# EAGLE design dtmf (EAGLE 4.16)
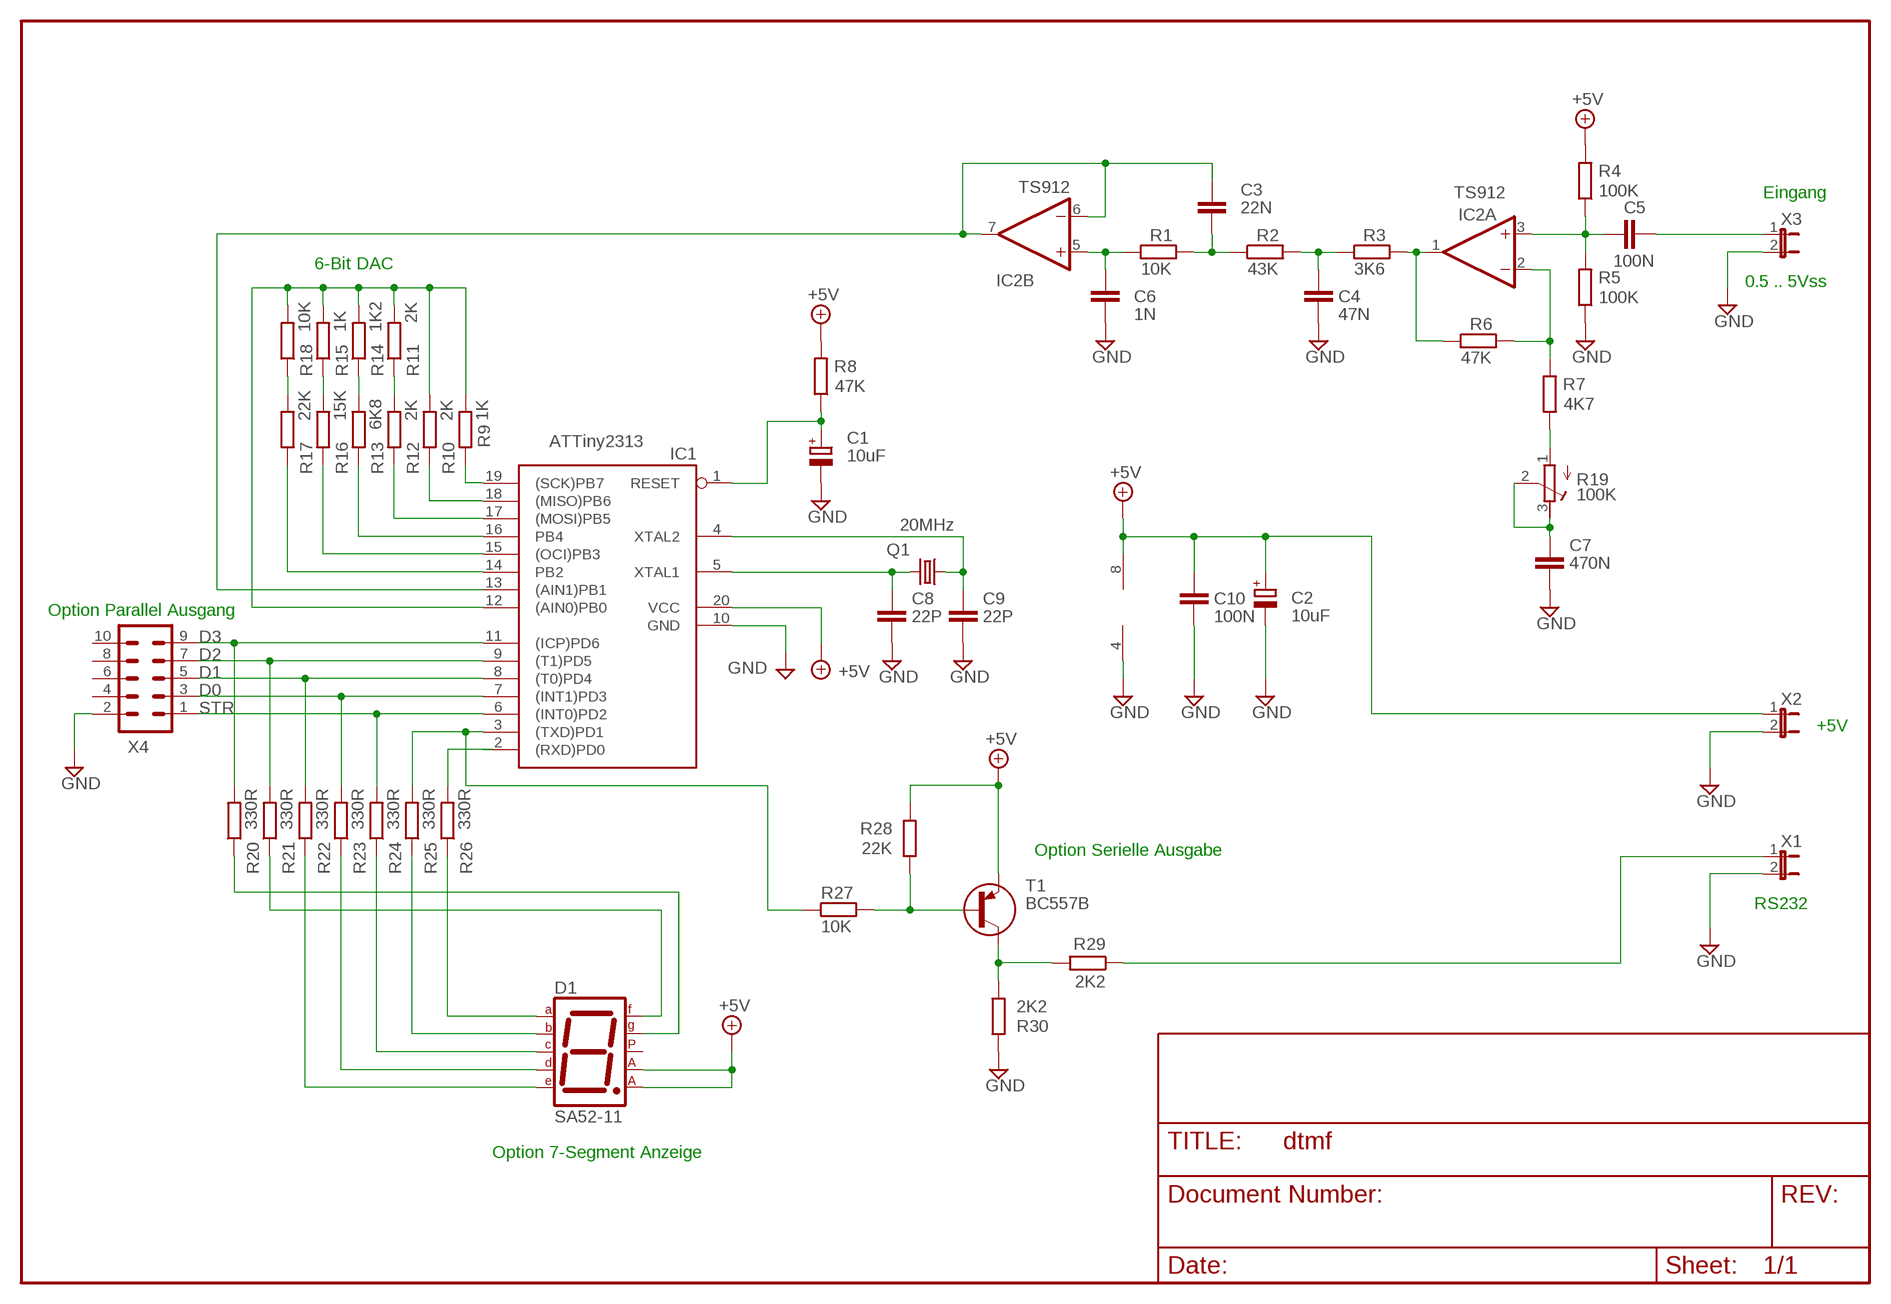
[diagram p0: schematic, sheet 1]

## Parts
C1  10uF  CPOL-EUE2.5-6  [E2,5-6]
C2  10uF  CPOL-EUE2.5-6  [E2,5-6]
C3  22N  C-EU050-025X075  [C050-025X075]
C4  47N  C-EU050-025X075  [C050-025X075]
C5  100N  C-EU050-025X075  [C050-025X075]
C6  1N  C-EU050-025X075  [C050-025X075]
C7  470N  C-EU050-025X075  [C050-025X075]
C8  22P  C-EU025-024X044  [C025-024X044]
C9  22P  C-EU025-024X044  [C025-024X044]
C10  100N  C-EU050-024X044  [C050-024X044]
D1  SA52-11  7SEG-CA  [7SEG-13]
IC1  ATTiny2313  AT90S2313P  [DIL20]
IC2  TS912  TLC272P  [DIL08]
Q1  20MHz  CRYSTALHC18U-V  [HC18U-V]
R1  10K  R-EU_0207/10  [0207/10]
R2  43K  R-EU_0207/10  [0207/10]
R3  3K6  R-EU_0207/10  [0207/10]
R4  100K  R-EU_0207/10  [0207/10]
R5  100K  R-EU_0207/10  [0207/10]
R6  47K  R-EU_0207/10  [0207/10]
R7  4K7  R-EU_0207/10  [0207/10]
R8  47K  R-EU_0207/10  [0207/10]
R9  1K  R-EU_0207/10  [0207/10]
R10  2K  R-EU_0207/10  [0207/10]
R11  2K  R-EU_0207/10  [0207/10]
R12  2K  R-EU_0207/10  [0207/10]
R13  6K8  R-EU_0207/10  [0207/10]
R14  1K2  R-EU_0207/10  [0207/10]
R15  1K  R-EU_0207/10  [0207/10]
R16  15K  R-EU_0207/10  [0207/10]
R17  22K  R-EU_0207/10  [0207/10]
R18  10K  R-EU_0207/10  [0207/10]
R19  100K  R-TRIMM64Y  [RTRIM64Y]
R20  330R  R-EU_0207/10  [0207/10]
R21  330R  R-EU_0207/10  [0207/10]
R22  330R  R-EU_0207/10  [0207/10]
R23  330R  R-EU_0207/10  [0207/10]
R24  330R  R-EU_0207/10  [0207/10]
R25  330R  R-EU_0207/10  [0207/10]
R26  330R  R-EU_0207/10  [0207/10]
R27  10K  R-EU_0207/10  [0207/10]
R28  22K  R-EU_0207/10  [0207/10]
R29  2K2  R-EU_0207/10  [0207/10]
R30  2K2  R-EU_0207/10  [0207/10]
T1  BC557B  BC559B-PNP-TO92-EBC  [TO92-EBC]
X1  JP1E  [JP1]
X2  JP1E  [JP1]
X3  JP1E  [JP1]
X4  MA05-2  [MA05-2]

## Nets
+5V: C2.+ C10.1 D1.3(CA1) D1.8(CA2) IC1.20(VCC) IC2.8(P:V+) R4.2 R8.2 R28.2 T1.E X2.1
D0: IC1.7((INT1)PD3) R23.2 X4.3
D1: IC1.8((T0)PD4) R22.2 X4.5
D2: IC1.9((T1)PD5) R21.2 X4.7
D3: IC1.11((ICP)PD6) R20.2 X4.9
GND: C1.- C2.- C4.2 C6.2 C7.2 C8.2 C9.2 C10.2 IC1.10(GND) IC2.4(P:V-) R5.1 R30.2 X1.2 X2.2 X3.2 X4.2
N$1: IC1.19((SCK)PB7) R9.1
N$2: IC1.18((MISO)PB6) R10.1
N$3: IC1.17((MOSI)PB5) R12.1
N$4: IC1.16(PB4) R13.1
N$5: IC1.15((OCI)PB3) R16.1
N$6: IC1.14(PB2) R17.1
N$7: R17.2 R18.1
N$8: R15.1 R16.2
N$9: R13.2 R14.1
N$10: R11.1 R12.2
N$11: IC1.12((AIN0)PB0) R9.2 R10.2 R11.2 R14.2 R15.2 R18.2
N$12: C7.1 R19.2(S) R19.3(A)
N$13: C1.+ IC1.1(RESET) R8.1
N$14: C9.1 IC1.4(XTAL2) Q1.1
N$15: C8.1 IC1.5(XTAL1) Q1.2
N$16: C3.1 IC1.13((AIN1)PB1) IC2.6(B:-IN) IC2.7(B:OUT)
N$18: C6.1 IC2.5(B:+IN) R1.1
N$19: C3.2 R1.2 R2.1
N$20: C4.1 R2.2 R3.1
N$21: IC2.1(A:OUT) R3.2 R6.1
N$22: C5.1 IC2.3(A:+IN) R4.1 R5.2
N$23: IC2.2(A:-IN) R6.2 R7.2
N$24: R7.1 R19.1(E)
N$29: IC1.3((TXD)PD1) R25.2 R27.1
N$30: IC1.2((RXD)PD0) R26.2
N$31: D1.7(A) R26.1
N$32: D1.6(B) R25.1
N$33: D1.4(C) R24.1
N$34: D1.2(D) R23.1
N$35: D1.1(E) R22.1
N$36: D1.9(F) R21.1
N$37: D1.10(G) R20.1
N$38: R27.2 R28.1 T1.B
N$40: R29.2 R30.1 T1.C
N$41: R29.1 X1.1
N$42: C5.2 X3.1
STR: IC1.6((INT0)PD2) R24.2 X4.1
Unconnected: D1.5(DP) X4.4 X4.6 X4.8 X4.10

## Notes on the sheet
- Eingang
- 6-Bit DAC
- 0.5 .. 5Vss
- Option Parallel Ausgang
- +5V
- Option Serielle Ausgabe
- RS232
- Option 7-Segment Anzeige

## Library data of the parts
C1 C2 = rcl:CPOL-EU: POLARIZED CAPACITOR, European symbol
C3-C10 = rcl:C-EU: CAPACITOR, European symbol
D1 = special:7SEG-CA: 7-segment DISPLAY single anode, 13 mm
IC1 = atmel:AT90S2313: MICROCONTROLLER 2 Kbytes FLASH 128 bytes SRAM 128 bytes EEPROM UART
IC2 = linear:TLC272: OP AMP
Q1 = crystal:CRYSTAL: CRYSTAL
R1-R18 R20-R30 = rcl:R-EU_: RESISTOR, European symbol
R19 = rcl:R-TRIMM: Trimm resistor
T1 = transistor:*-PNP-: PNP Transistror
X1-X3 = jumper:JP1E: JUMPER
X4 = con-lstb:MA05-2: PIN HEADER

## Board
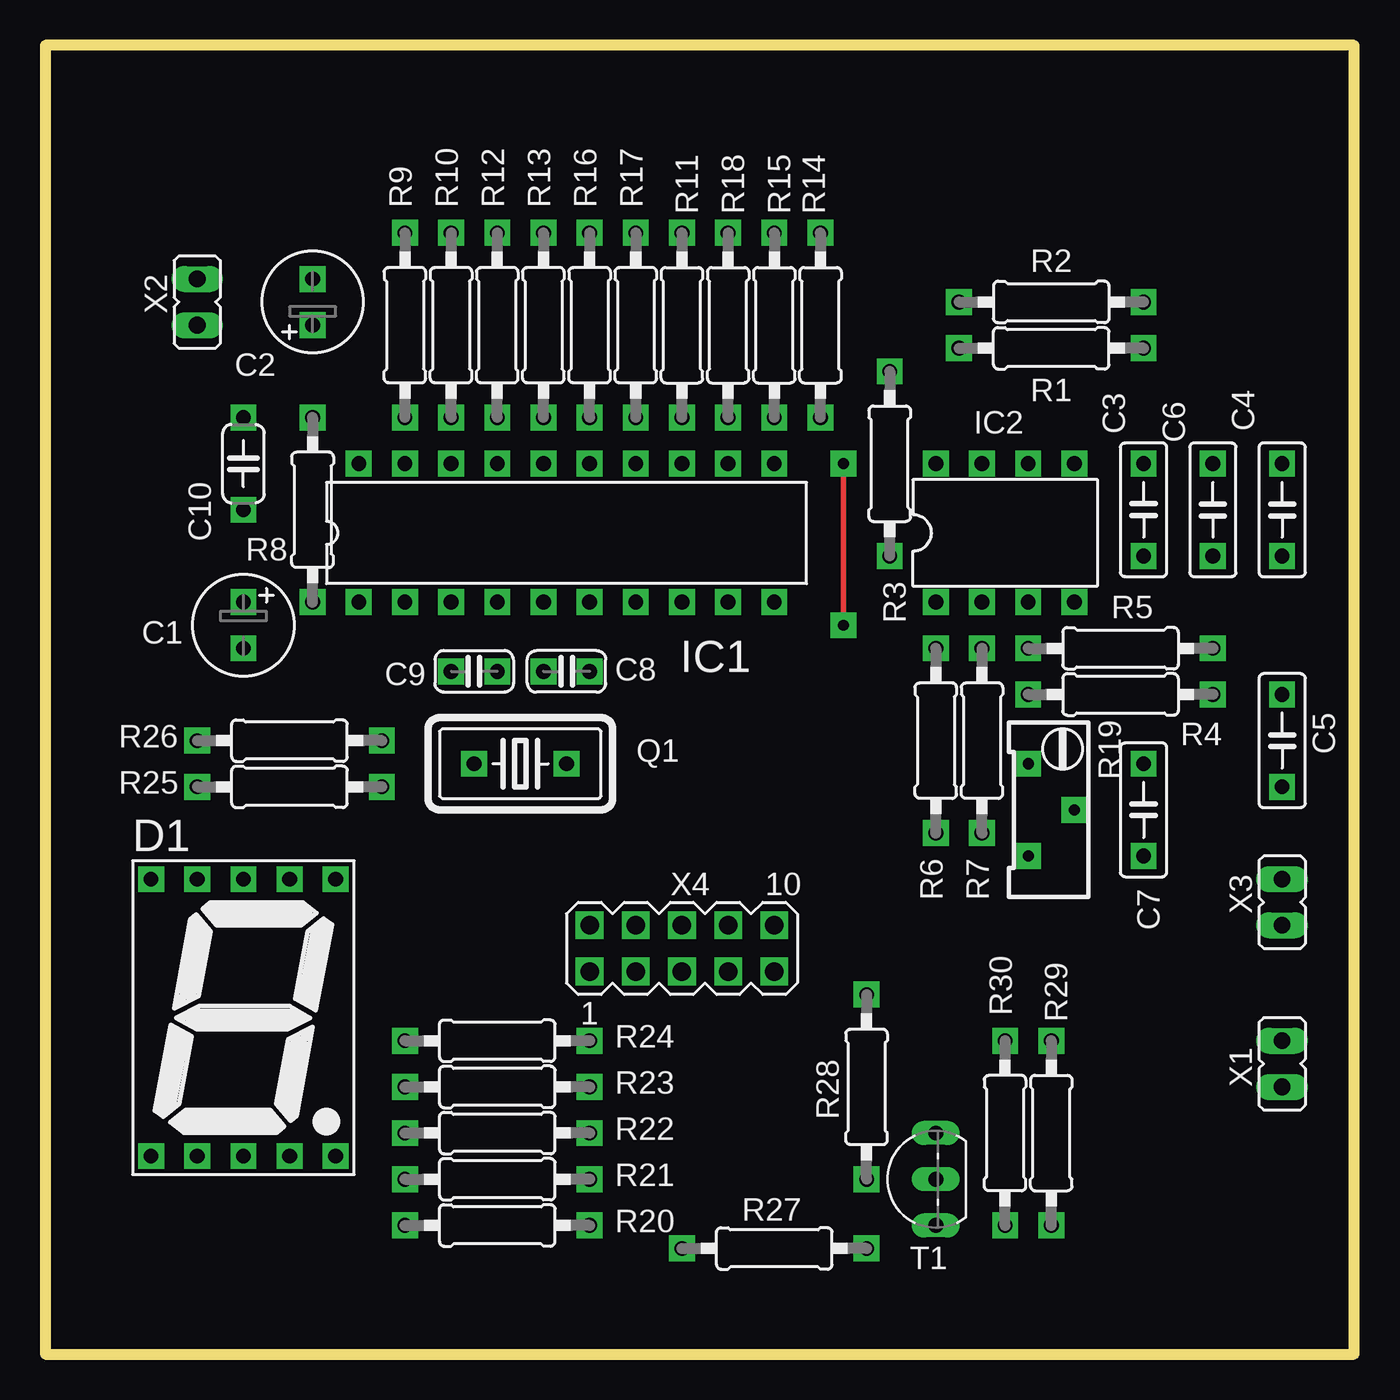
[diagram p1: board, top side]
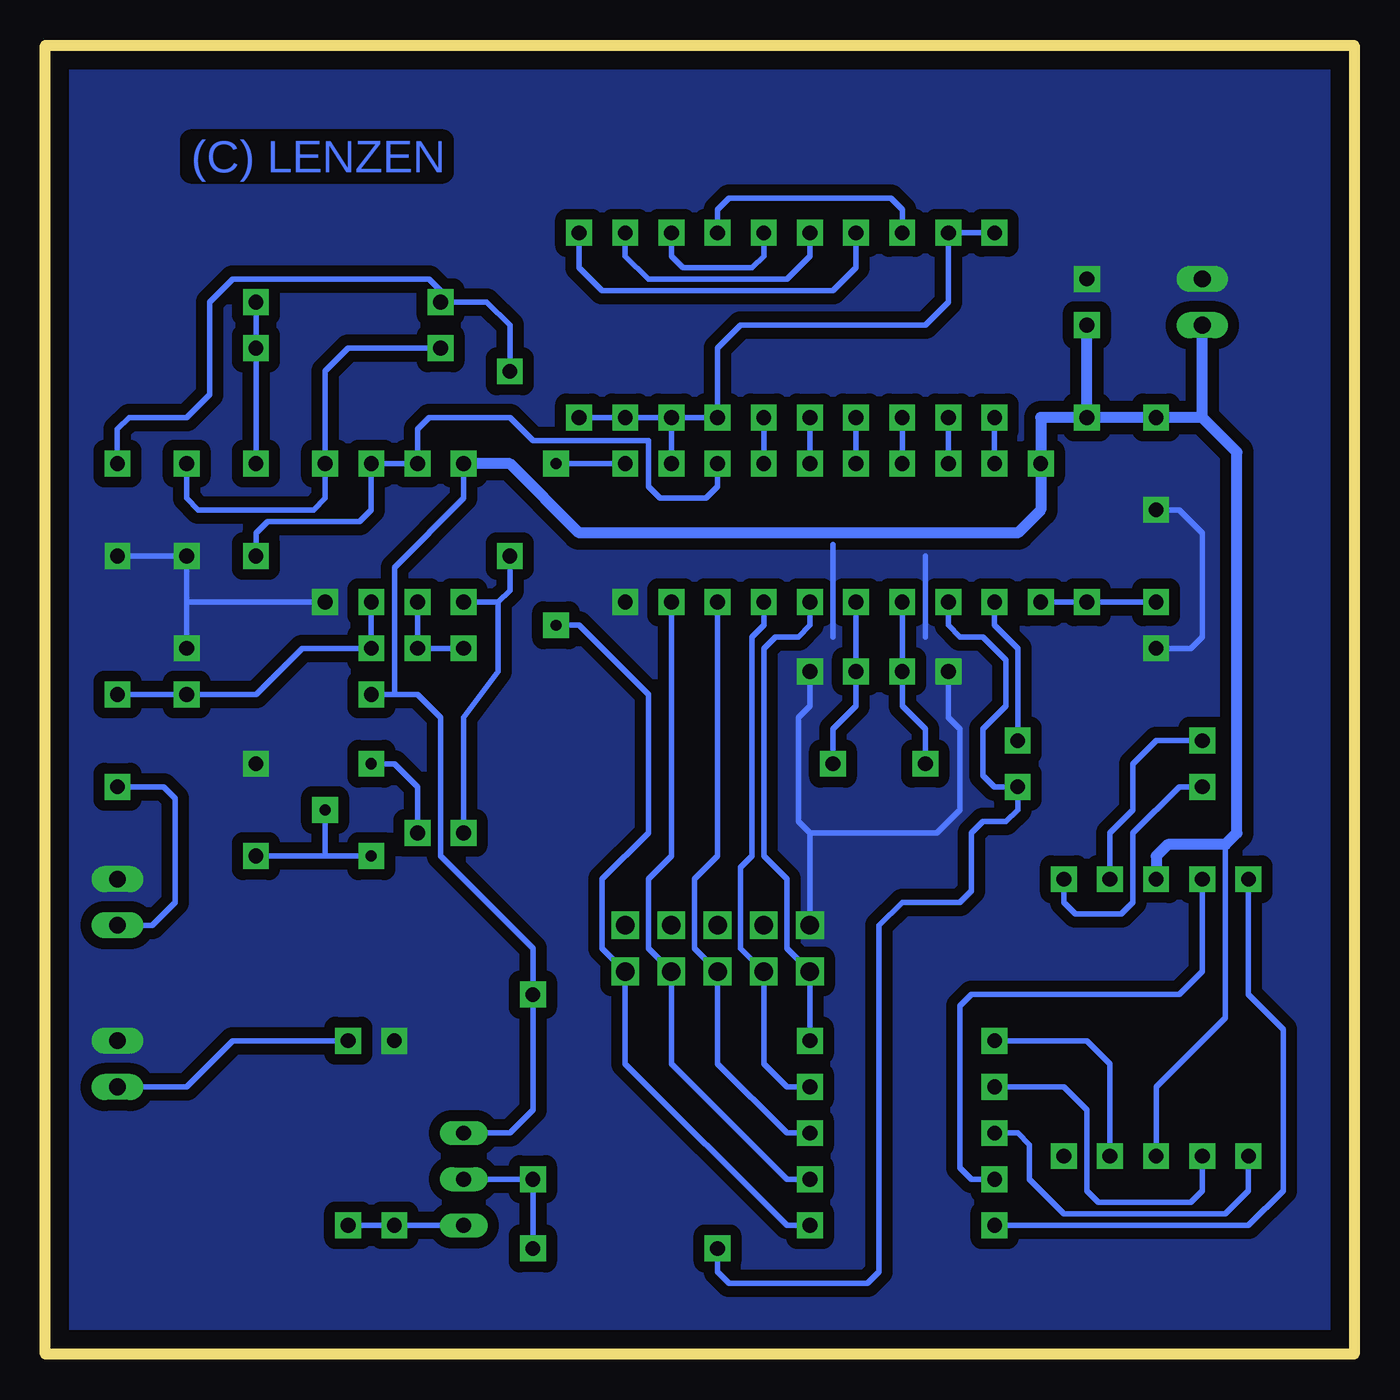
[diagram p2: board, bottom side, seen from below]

Size 72 x 72 mm. Coordinates in mm from the lower left corner, seen from the top.
Outline: 0,0 72,0 72,72 0,72 0,0
Copper layers (1*16): Top 0.035mm / dielectric 1.5mm / Bottom 0.035mm
Design rules "default": minimum track width 10mil, minimum drill 24mil, track to track 8mil, track to pad 8mil, pad to pad 8mil, via to via 8mil, smd to smd 8mil, copper to edge 40mil, drill to drill 8mil, minimum pad ring 10mil, minimum via ring 8mil, stop-mask expansion 4mil, vias tented up to drill 0mil, thermal gap 10mil

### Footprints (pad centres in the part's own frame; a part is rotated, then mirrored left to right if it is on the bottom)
E2,5-6 = drill 0.813 pad 1.422 square: + -1.27,0; - 1.27,0
C050-025X075 = drill 0.813 pad 1.422 square: 1 -2.54,0; 2 2.54,0
C025-024X044 = drill 0.813 pad 1.422 square: 1 -1.27,0; 2 1.27,0
C050-024X044 = drill 0.813 pad 1.422 square: 1 -2.54,0; 2 2.54,0
7SEG-13 = drill 0.813 pad 1.422 square: 1 -5.08,-7.62; 2 -2.54,-7.62; 3 0,-7.62; 4 2.54,-7.62; 5 5.08,-7.62; 6 5.08,7.62; 7 2.54,7.62; 8 0,7.62; 9 -2.54,7.62; 10 -5.08,7.62
DIL20 = drill 0.813 pad 1.422 square: 1 -11.43,-3.81; 2 -8.89,-3.81; 3 -6.35,-3.81; 4 -3.81,-3.81; 5 -1.27,-3.81; 6 1.27,-3.81; 7 3.81,-3.81; 8 6.35,-3.81; 9 8.89,-3.81; 10 11.43,-3.81; 11 11.43,3.81; 12 8.89,3.81; 13 6.35,3.81; 14 3.81,3.81; 15 1.27,3.81; 16 -1.27,3.81; 17 -3.81,3.81; 18 -6.35,3.81; 19 -8.89,3.81; 20 -11.43,3.81
DIL08 = drill 0.813 pad 1.422 square: 1 -3.81,-3.81; 2 -1.27,-3.81; 3 1.27,-3.81; 4 3.81,-3.81; 5 3.81,3.81; 6 1.27,3.81; 7 -1.27,3.81; 8 -3.81,3.81
HC18U-V = drill 0.813 pad 1.422 square: 1 -2.54,0; 2 2.54,0
0207/10 = drill 0.813 pad 1.422 square: 1 -5.08,0; 2 5.08,0
RTRIM64Y = drill 0.61 pad 1.422 square: 1 0,-2.54; 2 -2.54,0; 3 0,2.54
TO92-EBC = drill 0.813 long: B 0,-1.27; C -2.54,-1.27; E 2.54,-1.27
JP1 = drill 0.914 long: 1 0,-1.27; 2 0,1.27
MA05-2 = drill 1.016 square: 1 -5.08,-1.27; 2 -5.08,1.27; 3 -2.54,-1.27; 4 -2.54,1.27; 5 0,-1.27; 6 0,1.27; 7 2.54,-1.27; 8 2.54,1.27; 9 5.08,-1.27; 10 5.08,1.27

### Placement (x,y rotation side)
C1  10.89,40.1 270 top
C2  14.7,57.88 90 top
C3  60.42,46.45 90 top
C4  68.04,46.45 270 top
C5  68.04,33.75 270 top
C6  64.23,46.45 270 top
C7  60.42,29.94 90 top
C8  28.67,37.56 0 top
C9  23.59,37.56 180 top
C10  10.89,48.99 270 top
D1  10.89,18.51 0 top
IC1  28.67,45.18 0 top
IC2  52.8,45.18 0 top
Q1  26.13,32.48 0 top
R1  55.34,55.34 0 top
R2  55.34,57.88 180 top
R3  46.45,48.99 270 top
R4  59.15,36.29 180 top
R5  59.15,38.83 180 top
R6  48.99,33.75 90 top
R7  51.53,33.75 90 top
R8  14.7,46.45 90 top
R9  19.78,56.61 90 top
R10  22.32,56.61 90 top
R11  35.02,56.61 270 top
R12  24.86,56.61 90 top
R13  27.4,56.61 90 top
R14  42.64,56.61 270 top
R15  40.1,56.61 270 top
R16  29.94,56.61 90 top
R17  32.48,56.61 90 top
R18  37.56,56.61 270 top
R19  54.07,29.94 180 top
R20  24.86,7.08 0 top
R21  24.86,9.62 0 top
R22  24.86,12.16 0 top
R23  24.86,14.7 0 top
R24  24.86,17.24 0 top
R25  13.43,31.21 0 top
R26  13.43,33.75 0 top
R27  40.1,5.81 0 top
R28  45.18,14.7 90 top
R29  55.34,12.16 270 top
R30  52.8,12.16 90 top
T1  47.72,9.62 90 top
X1  68.04,15.97 0 top
X2  8.35,57.88 0 top
X3  68.04,24.86 0 top
X4  35.02,22.32 0 top

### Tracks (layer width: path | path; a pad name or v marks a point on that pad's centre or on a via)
+5V
  Bottom 0.305: D1.3 10.89,14.7 7.08,18.51 7.08,28.04 | T1.E 46.45,12.16 45.18,13.43 R28.2 45.18,22.32 50.26,27.4 50.26,35.02 51.53,36.29 52.8,36.29 | 52.8,36.29 R4.2 | 52.8,36.29 52.8,43.27 48.99,47.09 IC2.8
  Bottom 0.61: R8.2 17.24,51.53 IC1.20 17.24,46.45 18.51,45.18 42.64,45.18 46.45,48.99 IC2.8 | D1.8 10.89,27.4 10.26,28.04 7.08,28.04 6.45,28.67 6.45,49.62 8.35,51.53 | R8.2 C10.1 8.35,51.53 | R8.2 C2.+ | 8.35,51.53 X2.1
D0
  Bottom 0.305: IC1.7 32.48,40.1 33.12,39.47 33.12,27.4 33.75,26.77 33.75,22.32 X4.3 32.48,15.97 31.21,14.7 R23.2
D1
  Bottom 0.305: IC1.8 35.02,27.4 36.29,26.13 36.29,22.32 X4.5 35.02,15.97 31.21,12.16 R22.2
D2
  Bottom 0.305: IC1.9 37.56,27.4 38.83,26.13 38.83,22.32 X4.7 37.56,15.97 31.21,9.62 R21.2
D3  (via drill 0.6 pad 1.42)
  Top 0.305: v43.91,40.1 v43.91,48.99
  Bottom 0.305: R20.2 31.21,7.08 40.1,15.97 X4.9 41.37,22.32 41.37,26.13 38.83,28.67 38.83,36.29 42.64,40.1 v43.91,40.1 | v43.91,48.99 IC1.11
GND
  Bottom 0.305: IC2.4 64.23,41.37 | 64.23,41.37 C6.2 C4.2 | 64.23,41.37 R5.1 | C9.2 22.32,35.02 21.68,34.38 21.68,29.94 22.95,28.67 29.94,28.67 | C8.2 29.94,35.66 30.57,35.02 30.57,29.3 29.94,28.67 | 29.94,28.67 X4.2 | C10.2 9.62,46.45 8.35,45.18 8.35,39.47 8.98,38.83 C1.- | 23.59,39.47 23.59,43.91 | 28.67,39.47 28.67,44.55
  pour Bottom (isolate 0.61, no thermals): 0,71.31 71.58,71.31 71.58,0 0,0
N$1
  Bottom 0.305: IC1.19 R9.1
N$2
  Bottom 0.305: IC1.18 R10.1
N$3
  Bottom 0.305: IC1.17 R12.1
N$4
  Bottom 0.305: IC1.16 R13.1
N$5
  Bottom 0.305: IC1.15 R16.1
N$6
  Bottom 0.305: IC1.14 R17.1
N$7
  Bottom 0.305: R17.2 32.48,60.42 33.12,59.78 36.92,59.78 37.56,60.42 R18.1
N$8
  Bottom 0.305: R16.2 29.94,60.42 31.21,59.15 38.83,59.15 40.1,60.42 R15.1
N$9
  Bottom 0.305: R13.2 27.4,59.78 28.67,58.52 41.37,58.52 42.64,59.78 R14.1
N$10
  Bottom 0.305: R12.2 24.86,62.96 25.5,63.59 34.38,63.59 35.02,62.96 R11.1
N$11
  Bottom 0.305: R18.2 IC1.12 | R18.2 R11.2 35.02,55.34 33.75,56.61 23.59,56.61 22.32,57.88 R10.2 R9.2 | R18.2 R15.2 R14.2
N$12
  Bottom 0.305: R19.3 56.61,27.4 | 56.61,27.4 R19.2 | 56.61,27.4 C7.1
N$13
  Bottom 0.305: IC1.1 R8.1 C1.+
N$14
  Bottom 0.305: IC1.4 C9.1 24.86,35.66 23.59,34.38 Q1.1
N$15
  Bottom 0.305: IC1.5 C8.1 27.4,35.66 28.67,34.38 Q1.2
N$16
  Bottom 0.305: IC1.13 35.02,47.72 35.66,47.09 38.2,47.09 38.83,47.72 38.83,50.26 45.18,50.26 46.45,51.53 50.9,51.53 51.53,50.9 IC2.7 IC2.6 54.07,46.45 54.7,45.81 59.78,45.81 60.42,45.18 C3.1
N$18
  Bottom 0.305: R1.1 55.34,55.34 56.61,54.07 IC2.5 56.61,47.09 57.24,46.45 63.59,46.45 64.23,47.09 C6.1
N$19
  Bottom 0.305: C3.2 R1.2 R2.1
N$20
  Bottom 0.305: C4.1 68.04,50.9 67.41,51.53 64.23,51.53 62.96,52.8 62.96,57.88 61.69,59.15 50.9,59.15 50.26,58.52 R2.2 47.72,57.88 46.45,56.61 R3.1
N$21
  Bottom 0.305: R6.1 48.99,35.02 47.09,37.56 47.09,41.37 | R3.2 46.45,42.01 47.09,41.37 | 47.09,41.37 IC2.1
N$22
  Bottom 0.305: IC2.3 R5.2 57.88,38.83 60.42,36.29 R4.1 C5.1
N$23
  Bottom 0.305: R6.2 R7.2 IC2.2
N$24
  Bottom 0.305: R7.1 51.53,31.21 52.8,32.48 R19.1
N$29
  Bottom 0.305: IC1.3 22.32,40.1 21.68,39.47 20.41,39.47 19.14,38.2 19.14,35.66 20.41,34.38 20.41,31.84 19.78,31.21 R25.2 18.51,29.94 19.14,29.3 20.41,29.3 21.05,28.67 21.05,25.5 21.68,24.86 24.86,24.86 26.13,23.59 26.13,4.54 26.77,3.9 34.38,3.9 35.02,4.54 R27.1
N$30
  Bottom 0.305: R26.2 18.51,38.83 19.78,40.1 IC1.2
N$31
  Bottom 0.305: R26.1 10.89,33.75 12.16,32.48 12.16,29.94 13.43,28.67 D1.7
N$32
  Bottom 0.305: R25.1 9.62,31.21 12.16,28.67 12.16,24.86 12.79,24.23 15.34,24.23 15.97,24.86 D1.6
N$33
  Bottom 0.305: R24.1 14.7,17.24 13.43,15.97 D1.4
N$34
  Bottom 0.305: R23.1 15.97,14.7 14.7,13.43 14.7,8.98 14.06,8.35 8.98,8.35 8.35,8.98 D1.2
N$35
  Bottom 0.305: R22.1 18.51,12.16 17.88,11.53 17.88,9.62 15.97,7.71 7.08,7.71 5.81,8.98 D1.1
N$36
  Bottom 0.305: R21.1 21.05,9.62 21.68,10.26 21.68,19.14 21.05,19.78 9.62,19.78 8.35,21.05 D1.9
N$37
  Bottom 0.305: R20.1 5.81,7.08 3.9,8.98 3.9,17.88 5.81,19.78 D1.10
N$38
  Bottom 0.305: R27.2 R28.1 T1.B
N$40
  Bottom 0.305: T1.C R30.1 R29.2
N$41
  Bottom 0.305: R29.1 61.69,17.24 64.23,14.7 X1.1
N$42
  Bottom 0.305: X3.1 66.14,23.59 64.86,24.86 64.86,30.57 65.5,31.21 C5.2
STR
  Bottom 0.305: IC1.6 29.94,40.1 30.57,39.47 31.84,39.47 32.48,38.83 32.48,27.4 31.21,26.13 31.21,22.32 X4.1 R24.2

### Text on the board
Bottom: (C) LENZEN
